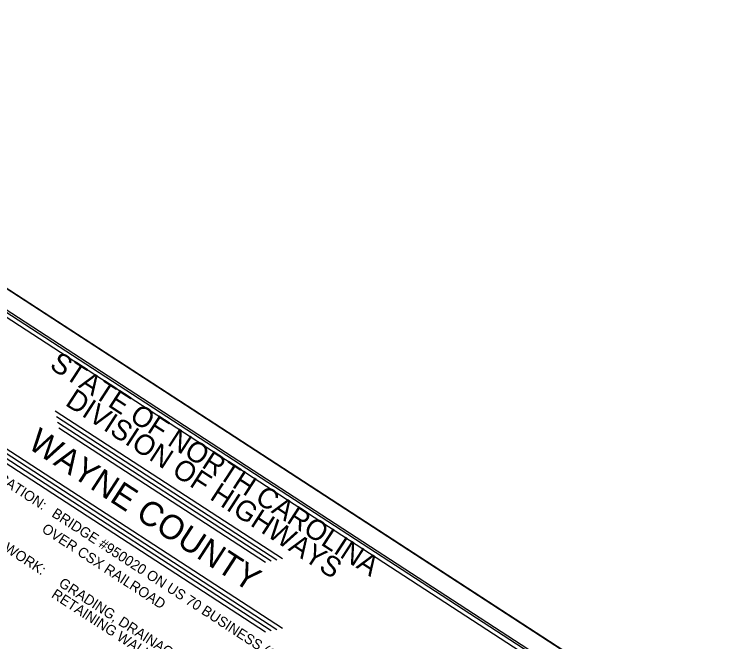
# Model space of a CAD drawing. Extents: x 2291197 to 2302790, y 592892 to 604246.
# Drawn here: x 2298300 to 2301839, y 601165 to 604246 of the extents above; entities that cross this region are included whole.
import ezdxf

# ---------------------------------------------------------------- set-up
doc = ezdxf.new("R2010")
doc.units = 0
for name, color, linetype in [('Sheet Cutting Line CELL', 7, 'Continuous'), ('Sheet Data Field CELL', 7, 'Continuous'), ('Sheet Plot Border Inside CELL', 7, 'Continuous'), ('Sheet Plot Border Outside CELL', 7, 'Continuous'), ('Sheet Title CELL', 7, 'Continuous'), ('Sheet Title Data Points CELL', 7, 'Continuous')]:
    doc.layers.add(name, color=color, linetype=linetype)

msp = doc.modelspace()

# ---------------------------------------------------------------- linework, layer by layer
at = {"layer": 'Sheet Cutting Line CELL'}
msp.add_line((2296191.6, 604246.1), (2301839.2, 600574.8), dxfattribs=at)
at = {"layer": 'Sheet Plot Border Inside CELL'}
msp.add_lwpolyline([(2293886.1, 600604), (2299475, 596970.9), (2301775.2, 600509.4), (2296186.3, 604142.5)], close=True, dxfattribs=at)
at = {"layer": 'Sheet Plot Border Outside CELL'}
msp.add_lwpolyline([(2301839.2, 600574.8), (2296191.6, 604246.1), (2293793.6, 600557.1), (2299441.2, 596885.8)], close=True, dxfattribs=at)
at = {"layer": 'Sheet Title CELL'}
for p, q in [((2298500.9, 602298.6), (2299616.9, 601573.2)), ((2298506.8, 602271), (2299589.2, 601567.3)), ((2298512.7, 602243.3), (2299561.6, 601561.5)), ((2298518.5, 602215.6), (2299533.9, 601555.6)), ((2298188.4, 602160.2), (2299617.1, 601231.5)), ((2298194.3, 602132.6), (2299589.4, 601225.6)), ((2298200.1, 602104.9), (2299561.7, 601219.8)), ((2298206, 602077.2), (2299534.1, 601213.9))]:
    msp.add_line(p, q, dxfattribs=at)
for points in [[(2301694.2, 600549.8), (2296730.7, 603776.5)], [(2301666.5, 600544), (2296904.3, 603639.7)]]:
    msp.add_lwpolyline(points, dxfattribs=at)
at = {"layer": 'Sheet Title Data Points CELL'}
msp.add_line((2299224.5, 601298.4), (2299224.5, 601298.4), dxfattribs=at)

# ---------------------------------------------------------------- texts
at = {"layer": 'Sheet Data Field CELL'}
for s, height, p in [('WAYNE COUNTY', 120, (2298359.7, 602120)), ('BRIDGE #950020 ON US 70 BUSINESS (GRANTHAM ST)', 50, (2298479.6, 601782.7)), ('OVER CSX RAILROAD', 50, (2298430.6, 601707.3)), ('GRADING, DRAINAGE, PAVING, STRUCTURE, ', 50, (2298513.9, 601440.7)), ('RETAINING WALLS, AND SIGNALS', 50, (2298478.1, 601385.7))]:
    msp.add_text(s, height=height, rotation=326.9737, dxfattribs=at).set_placement(p)
at = {"layer": 'Sheet Title CELL'}
for s, height, p in [('STATE OF NORTH CAROLINA', 100, (2298468, 602510.7)), ('DIVISION OF HIGHWAYS', 100, (2298545.2, 602329.3)), ('LOCATION: ', 50, (2298136.6, 602005.7)), ('TYPE OF WORK:', 50, (2297989.4, 601779.3))]:
    msp.add_text(s, height=height, rotation=326.9737, dxfattribs=at).set_placement(p)

doc.saveas('drawing.dxf')
